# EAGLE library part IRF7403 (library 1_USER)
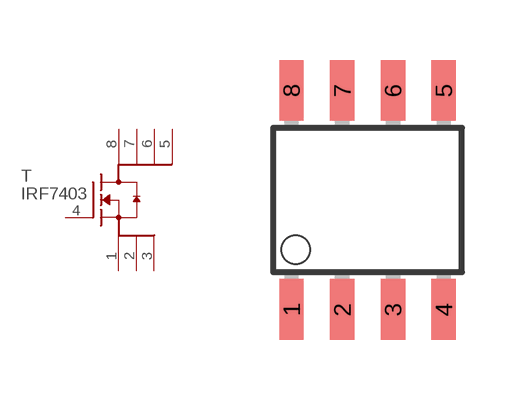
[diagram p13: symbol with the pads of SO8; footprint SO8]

Designator prefix T

## IRF7403  [SO8]
1  S  pas
2  S  pas
3  S  pas
4  G  pas
5  D  pas
6  D  pas
7  D  pas
8  D  pas

## Footprint SO8 (pad centres in mm)
smd 0.61 x 1.524: 1 -1.27,-2.743; 2 0,-2.743; 3 1.27,-2.743; 4 2.54,-2.743; 5 2.54,2.743; 6 1.27,2.743; 7 0,2.743; 8 -1.27,2.743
